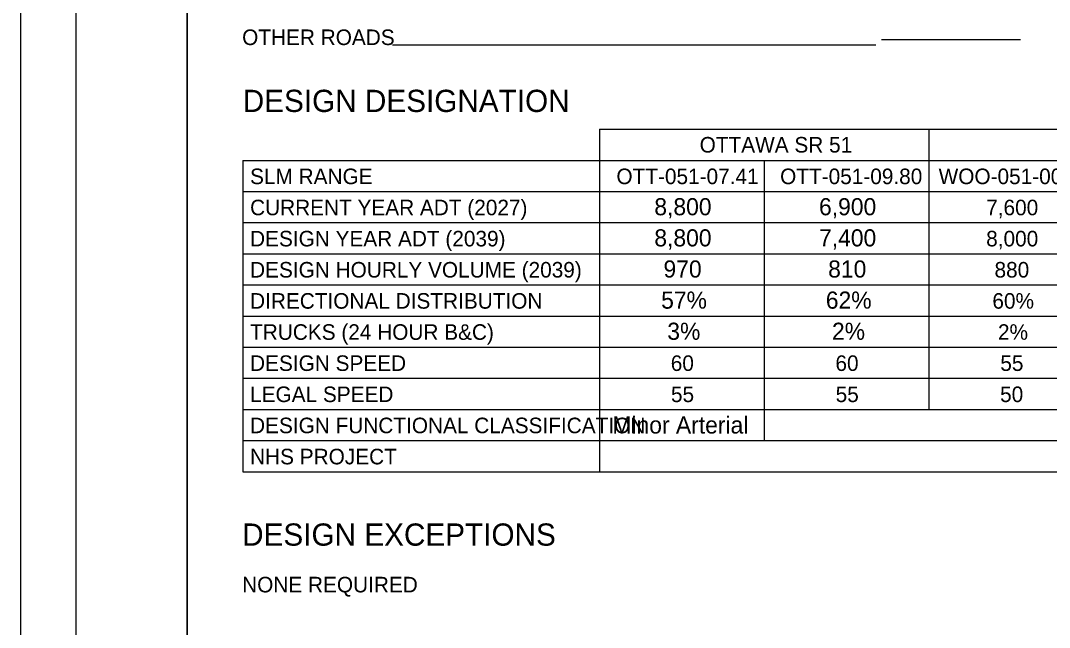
# Model space of a CAD drawing. Extents: x 0 to 34, y 0 to 22.
# Drawn here: x 0 to 9.26, y 5.64 to 11.1 of the extents above; entities that cross this region are included whole.
import ezdxf

# ---------------------------------------------------------------- set-up
doc = ezdxf.new("R2010")
doc.units = 0
for name, color, linetype in [('SH_Border', 7, 'Continuous'), ('SH_Cut_Line', 7, 'Continuous'), ('SH_Data', 7, 'Continuous'), ('SH_Text', 7, 'Continuous')]:
    doc.layers.add(name, color=color, linetype=linetype)

msp = doc.modelspace()

# ---------------------------------------------------------------- linework, layer by layer
at = {"layer": 'SH_Border'}
for points in [[(0.5, 21.5), (1.5, 21.5), (1.5, 0.5), (0.5, 0.5)], [(1.5, 21.5), (33.5, 21.5), (33.5, 0.5), (1.5, 0.5)]]:
    msp.add_lwpolyline(points, close=True, dxfattribs=at)
at = {"layer": 'SH_Cut_Line'}
msp.add_lwpolyline([(0, 0), (34, 0), (34, 22), (0, 22)], close=True, dxfattribs=at)
at = {"layer": 'SH_Data'}
for p, q in [((7.7, 10.8767), (3.3471, 10.8767)), ((9, 10.9223), (7.75, 10.9223)), ((5.2118, 10.12), (14.1059, 10.12)), ((5.2118, 10.12), (5.2118, 7.04)), ((8.1765, 10.12), (8.1765, 7.6)), ((2, 9.84), (14.1059, 9.84)), ((2, 9.84), (2, 7.04)), ((6.6941, 9.84), (6.6941, 7.32)), ((2, 9.56), (14.1059, 9.56)), ((2, 9.28), (14.1059, 9.28)), ((2, 9), (14.1059, 9)), ((2, 8.72), (14.1059, 8.72)), ((2, 8.44), (14.1059, 8.44)), ((2, 8.16), (14.1059, 8.16)), ((2, 7.88), (14.1059, 7.88)), ((2, 7.6), (14.1059, 7.6)), ((2, 7.32), (14.1059, 7.32)), ((2, 7.04), (14.1059, 7.04))]:
    msp.add_line(p, q, dxfattribs=at)

# ---------------------------------------------------------------- texts
msp.add_text('DESIGN DESIGNATION', height=0.2, dxfattribs=at).set_placement((2, 10.2747))
at = {"layer": 'SH_Text'}
for s, height, p in [('OTHER ROADS', 0.14, (1.9944, 10.8767)), ('OTTAWA SR 51', 0.14, (6.1128, 9.91)), ('SLM RANGE', 0.14, (2.0659, 9.6259)), ('OTT-051-07.41', 0.14, (5.3636, 9.6259)), ('OTT-051-09.80', 0.14, (6.8371, 9.6259)), ('WOO-051-00.19', 0.14, (8.2639, 9.6259)), ('CURRENT YEAR ADT (2027)', 0.14, (2.0659, 9.3459)), ('8,800', 0.154, (5.7047, 9.3459)), ('6,900', 0.154, (7.1871, 9.3459)), ('7,600', 0.14, (8.692, 9.3459)), ('DESIGN YEAR ADT (2039)', 0.14, (2.0659, 9.0659)), ('8,800', 0.154, (5.7047, 9.0659)), ('7,400', 0.154, (7.1871, 9.0659)), ('8,000', 0.14, (8.692, 9.0659)), ('DESIGN HOURLY VOLUME (2039)', 0.14, (2.0659, 8.7859)), ('970', 0.154, (5.7873, 8.7859)), ('810', 0.154, (7.2696, 8.7859)), ('880', 0.14, (8.767, 8.7859)), ('DIRECTIONAL DISTRIBUTION', 0.14, (2.0659, 8.5059)), ('57%', 0.154, (5.7662, 8.5059)), ('62%', 0.154, (7.2485, 8.5059)), ('60%', 0.14, (8.7479, 8.5059)), ('TRUCKS (24 HOUR B&C)', 0.14, (2.0659, 8.2259)), ('3%', 0.154, (5.8215, 8.2259)), ('2%', 0.154, (7.3039, 8.2259)), ('2%', 0.14, (8.7982, 8.2259)), ('DESIGN SPEED', 0.14, (2.0659, 7.9459)), ('60', 0.14, (5.8526, 7.9459)), ('60', 0.14, (7.335, 7.9459)), ('55', 0.14, (8.8192, 7.9459)), ('LEGAL SPEED', 0.14, (2.0659, 7.6659)), ('55', 0.14, (5.8545, 7.6659)), ('55', 0.14, (7.3369, 7.6659)), ('50', 0.14, (8.8173, 7.6659)), ('DESIGN FUNCTIONAL CLASSIFICATION', 0.14, (2.0659, 7.3859)), ('Minor Arterial', 0.154, (5.327, 7.383)), ('NHS PROJECT', 0.14, (2.0659, 7.1059)), ('DESIGN EXCEPTIONS', 0.2, (1.9944, 6.3744)), ('NONE REQUIRED', 0.14, (1.9944, 5.9544))]:
    msp.add_text(s, height=height, dxfattribs=at).set_placement(p)

doc.saveas('drawing.dxf')
